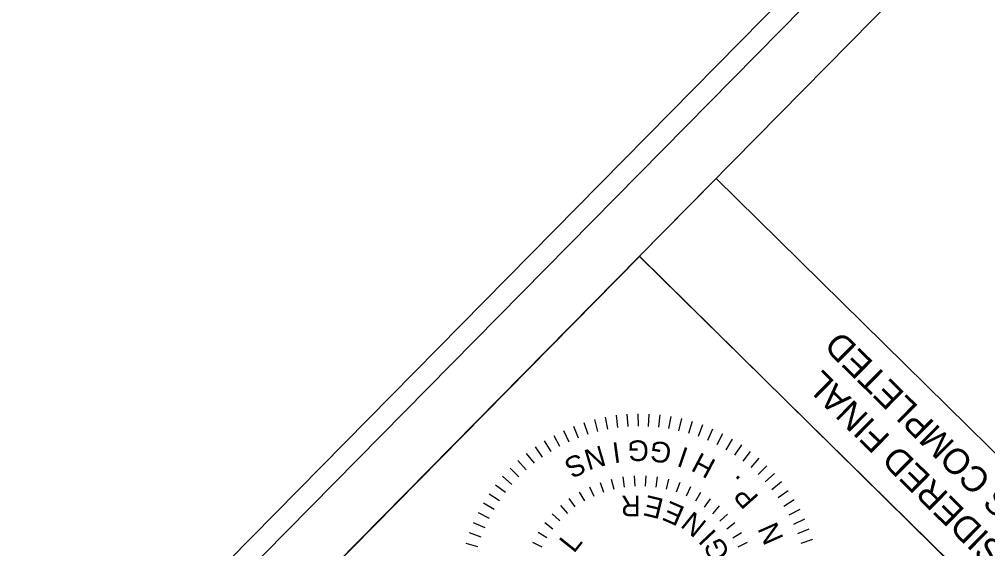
# Model space of a CAD drawing. Extents: x 1265903 to 1267873, y 771347 to 773361.
# Drawn here: x 1265903.3 to 1266111.2, y 772576.6 to 772690.3 of the extents above; entities that cross this region are included whole.
import ezdxf

# ---------------------------------------------------------------- set-up
doc = ezdxf.new("R2010")
doc.units = 0
for name, color, linetype in [('Default', 7, 'Continuous'), ('Exist Utilities Power UG Cable SUE LOS B Cogo Comment', 7, 'Continuous'), ('Prop Conc 1ft 6in Curb and Gutter', 7, 'Continuous'), ('Prop Conc 5in Monolithic Keyed In Island', 7, 'Continuous'), ('Prop EOT', 7, 'Continuous'), ('Prop Horizontal Alignment Station Label', 7, 'Continuous')]:
    doc.layers.add(name, color=color, linetype=linetype)

msp = doc.modelspace()

# ---------------------------------------------------------------- linework, layer by layer
at = {"layer": 'Default'}
for p, q in [((1266026.77, 772604.3), (1266027.43, 772601.73)), ((1266029.07, 772604.82), (1266029.58, 772602.21)), ((1266031.4, 772605.2), (1266031.74, 772602.56)), ((1266033.74, 772605.43), (1266033.93, 772602.78)), ((1266036.1, 772605.53), (1266036.12, 772602.87)), ((1266038.45, 772605.48), (1266038.32, 772602.82)), ((1266040.8, 772605.29), (1266040.51, 772602.65)), ((1266043.13, 772604.96), (1266042.68, 772602.34)), ((1266045.44, 772604.49), (1266044.83, 772601.9)), ((1266022.29, 772602.85), (1266023.26, 772600.38)), ((1266024.51, 772603.65), (1266025.33, 772601.12)), ((1266047.72, 772603.88), (1266046.95, 772601.33)), ((1266049.95, 772603.13), (1266049.03, 772600.63)), ((1266052.14, 772602.25), (1266051.07, 772599.81)), ((1266018.01, 772600.88), (1266019.28, 772598.54)), ((1266020.12, 772601.93), (1266021.24, 772599.52)), ((1266054.27, 772601.24), (1266053.05, 772598.87)), ((1266056.34, 772600.1), (1266054.98, 772597.81)), ((1266014.01, 772598.41), (1266015.54, 772596.23)), ((1266015.97, 772599.7), (1266017.37, 772597.44)), ((1266058.33, 772598.84), (1266056.84, 772596.64)), ((1266012.12, 772596.99), (1266013.78, 772594.92)), ((1266060.23, 772597.46), (1266058.62, 772595.36)), ((1266062.06, 772595.97), (1266060.32, 772593.97)), ((1266008.63, 772593.83), (1266010.53, 772591.97)), ((1266010.33, 772595.46), (1266012.11, 772593.49)), ((1266063.79, 772594.37), (1266061.93, 772592.47)), ((1266007.03, 772592.1), (1266009.03, 772590.35)), ((1266032.82, 772591.97), (1266033.14, 772589.78)), ((1266035.3, 772592.2), (1266035.4, 772589.99)), ((1266037.78, 772592.2), (1266037.67, 772589.98)), ((1266040.25, 772591.95), (1266039.93, 772589.76)), ((1266065.42, 772592.67), (1266063.45, 772590.89)), ((1266005.54, 772590.27), (1266007.64, 772588.66)), ((1266025.7, 772589.86), (1266026.63, 772587.85)), ((1266028, 772590.79), (1266028.73, 772588.7)), ((1266030.38, 772591.5), (1266030.91, 772589.35)), ((1266042.69, 772591.47), (1266042.15, 772589.32)), ((1266045.07, 772590.75), (1266044.33, 772588.66)), ((1266047.37, 772589.81), (1266046.43, 772587.8)), ((1266066.95, 772590.88), (1266064.88, 772589.22)), ((1266004.16, 772588.36), (1266006.36, 772586.87)), ((1266023.5, 772588.71), (1266024.62, 772586.8)), ((1266049.56, 772588.65), (1266048.44, 772586.74)), ((1266068.37, 772589), (1266066.19, 772587.46)), ((1266002.9, 772586.37), (1266005.19, 772585.02)), ((1266019.47, 772585.8), (1266020.94, 772584.14)), ((1266022.65, 772585.51), (1266021.35, 772587.31)), ((1266051.64, 772587.28), (1266050.33, 772585.5)), ((1266053.57, 772585.73), (1266052.1, 772584.07)), ((1266069.66, 772587.03), (1266067.41, 772585.63)), ((1266001.76, 772584.31), (1266004.13, 772583.09)), ((1266017.69, 772584.07), (1266019.31, 772582.56)), ((1266055.35, 772583.99), (1266053.72, 772582.48)), ((1266070.85, 772584.99), (1266068.5, 772583.72)), ((1266000.75, 772582.18), (1266003.19, 772581.11)), ((1266016.09, 772582.18), (1266017.84, 772580.83)), ((1266056.94, 772582.08), (1266055.18, 772580.74)), ((1266071.9, 772582.88), (1266069.48, 772581.76)), ((1265999.87, 772579.99), (1266002.37, 772579.07)), ((1266014.67, 772580.13), (1266016.55, 772578.96)), ((1266056.47, 772578.86), (1266058.36, 772580.02)), ((1266072.81, 772580.71), (1266070.34, 772579.74)), ((1265999.12, 772577.76), (1266001.67, 772576.99)), ((1266013.46, 772577.97), (1266015.44, 772576.98)), ((1266059.55, 772577.86), (1266057.56, 772576.89)), ((1266073.61, 772578.49), (1266071.08, 772577.67))]:
    msp.add_line(p, q, dxfattribs=at)
at = {"layer": 'Exist Utilities Power UG Cable SUE LOS B Cogo Comment'}
msp.add_lwpolyline([(1266028.73, 772489.08), (1265957.52, 772559.24), (1266036.45, 772639.35), (1266107.66, 772569.19)], close=True, dxfattribs=at)
at = {"layer": 'Prop Conc 1ft 6in Curb and Gutter'}
msp.add_line((1265957.52, 772559.24), (1266036.48, 772639.4), dxfattribs=at)
msp.add_lwpolyline([(1265931.14, 772532.52), (1266999.64, 771479.71), (1267736.59, 772227.64), (1266668.1, 773280.44)], close=True, dxfattribs=at)
at = {"layer": 'Prop Conc 5in Monolithic Keyed In Island'}
for p, q in [((1266036.4, 772639.37), (1266052.9, 772656.11)), ((1266036.4, 772639.37), (1266052.9, 772656.11)), ((1266052.89, 772656.1), (1266195.4, 772515.73)), ((1266052.89, 772656.1), (1266195.4, 772515.73)), ((1266178.91, 772498.99), (1266036.4, 772639.36)), ((1266178.91, 772498.99), (1266036.4, 772639.36))]:
    msp.add_line(p, q, dxfattribs=at)
at = {"layer": 'Prop EOT'}
msp.add_lwpolyline([(1267847.69, 772121.71), (1266660.96, 773290.98), (1265920.5, 772539.5), (1267107.23, 771370.21)], close=True, dxfattribs=at)
at = {"layer": 'Prop Horizontal Alignment Station Label'}
msp.add_lwpolyline([(1267870.98, 772126.83), (1266671.79, 773308.41), (1265903.26, 772528.42), (1267102.45, 771346.84)], close=True, dxfattribs=at)

# ---------------------------------------------------------------- texts
at = {"layer": 'Default'}
for s, rotation, p in [('N', 196.5624, (1266028.29, 772598.81)), ('I', 187.7698, (1266031.98, 772599.5)), ('G', 178.8872, (1266038.49, 772599.77)), ('G', 170.0045, (1266043.6, 772599.06)), ('I', 161.1819, (1266047.22, 772598.02)), ('S', 205.2352, (1266023.52, 772597.2)), ('H', 152.1794, (1266053.12, 772595.37)), ('.', 139.395, (1266058.41, 772591.56)), ('R', 180.1276, (1266036.69, 772587.92)), ('E', 166.3565, (1266041.87, 772587.17)), ('P', 131.6527, (1266062.25, 772587.62)), ('E', 156.3707, (1266046.43, 772585.34)), ('N', 140.9786, (1266051.13, 772582.12)), ('N', 113.8574, (1266067.47, 772578.73)), ('I', 133.3489, (1266053.17, 772579.91)), ('L', 51.4334, (1266022.34, 772575.41)), ('G', 115.2541, (1266055.95, 772575.21))]:
    msp.add_text(s, height=4.43, rotation=rotation, dxfattribs=at).set_placement(p)
at = {"layer": 'Prop Conc 5in Monolithic Keyed In Island'}
for s, p in [('UNLESS ALL SIGNATURES COMPLETED', (1266180.95, 772523.86)), ('UNLESS ALL SIGNATURES COMPLETED', (1266180.95, 772523.86)), ('DOCUMENT NOT CONSIDERED FINAL', (1266171.16, 772521.15)), ('DOCUMENT NOT CONSIDERED FINAL', (1266171.16, 772521.15))]:
    msp.add_text(s, height=5.5, rotation=135.4338, dxfattribs=at).set_placement(p)

doc.saveas('drawing.dxf')
